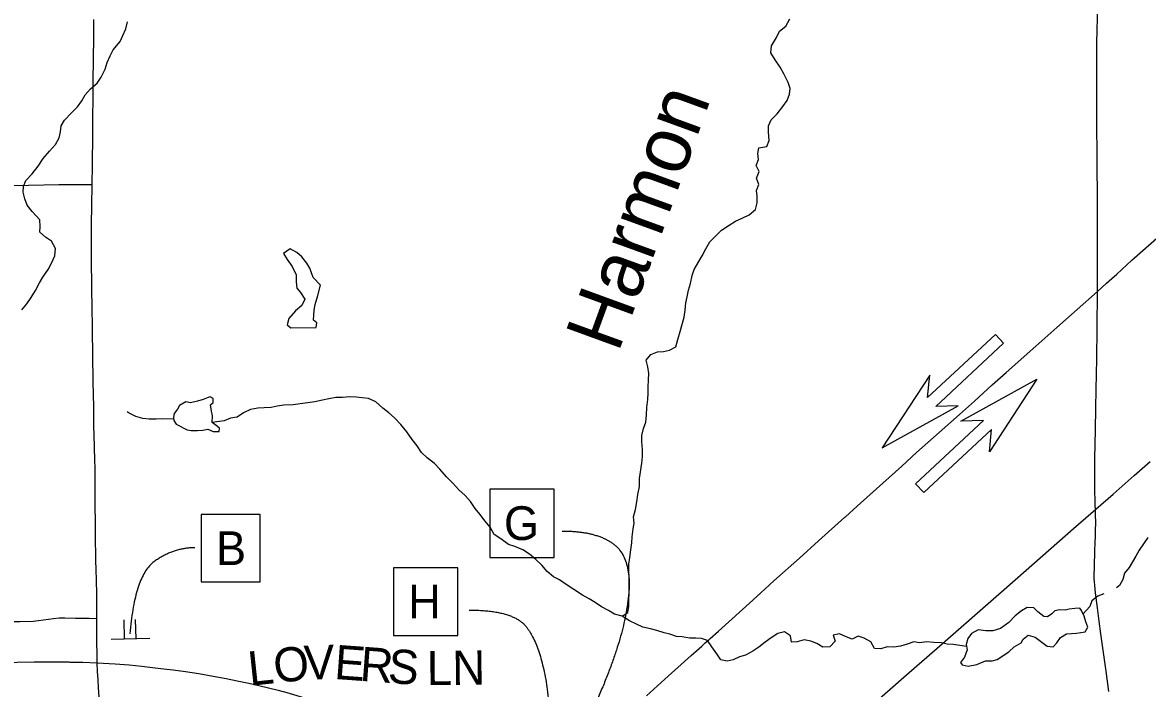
# Model space of a CAD drawing. Extents: x 0 to 34, y 0 to 22.
# Drawn here: x 2.507 to 7.177, y 6.648 to 9.413 of the extents above; entities that cross this region are included whole.
import ezdxf

# ---------------------------------------------------------------- set-up
doc = ezdxf.new("R2010")
doc.units = 0
for name, color, linetype in [('GM_X_City_Street', 7, 'Continuous'), ('GM_X_County_Road', 7, 'Continuous'), ('GM_X_County_Road_Text', 7, 'Continuous'), ('GM_X_Minor_Lake', 7, 'Continuous'), ('GM_X_Minor_River', 7, 'Continuous'), ('GM_X_Minor_River_Text', 7, 'Continuous'), ('GM_X_Rail_Line', 7, 'Continuous'), ('GM_X_State_Route', 7, 'Continuous'), ('GM_X_Township_Road', 7, 'Continuous'), ('PM_P_Cells', 7, 'Continuous'), ('SH_Text', 7, 'Continuous'), ('SN_P_Signs', 7, 'Continuous')]:
    doc.layers.add(name, color=color, linetype=linetype)

msp = doc.modelspace()

# ---------------------------------------------------------------- linework, layer by layer
at = {"layer": 'GM_X_City_Street'}
msp.add_lwpolyline([(2.1137, 6.9234), (2.2411, 6.9239), (2.3094, 6.9254), (2.3839, 6.9269), (2.4568, 6.927), (2.4957, 6.9269), (2.5516, 6.9283), (2.5732, 6.9304), (2.6362, 6.9394), (2.6593, 6.9416), (2.6826, 6.9422), (2.727, 6.941), (2.7835, 6.9399), (2.8154, 6.9392)], dxfattribs=at)
at = {"layer": 'GM_X_County_Road'}
for points in [[(6.9691, 8.2961), (6.9698, 8.5029), (6.9698, 8.5248), (6.9697, 8.5601), (6.9694, 8.6093), (6.9695, 8.6402), (6.9679, 8.8711), (6.9668, 8.9812), (6.9662, 9.0699), (6.9664, 9.1041), (6.9661, 9.1475), (6.9663, 9.1956), (6.9665, 9.2622), (6.9667, 9.3286), (6.9706, 9.4838)], [(6.9604, 7.4147), (6.9589, 7.4813), (6.9591, 7.6037), (6.961, 7.7219), (6.9626, 7.812), (6.9636, 7.8897), (6.9662, 8.0172), (6.9685, 8.1446), (6.9691, 8.2961)], [(7.0166, 6.6358), (7.0053, 6.7207), (6.9833, 6.8756), (6.9767, 6.928), (6.9696, 6.9835), (6.9614, 7.0451), (6.958, 7.0755), (6.9566, 7.0932), (6.9563, 7.1018), (6.9563, 7.1151), (6.957, 7.155), (6.9589, 7.2195), (6.9603, 7.2537), (6.9612, 7.2826), (6.9615, 7.2985), (6.962, 7.3418), (6.9618, 7.3648), (6.9612, 7.3858), (6.9604, 7.4147)], [(2.8208, 6.6847), (2.8191, 6.7188), (2.8178, 6.755)], [(2.827, 6.5951), (2.8224, 6.6514), (2.8208, 6.6847)]]:
    msp.add_lwpolyline(points, dxfattribs=at)
at = {"layer": 'GM_X_Minor_Lake'}
for p, q in [((3.6217, 8.1462), (3.7258, 8.1465)), ((3.1453, 7.7459), (3.191, 7.7218)), ((6.6015, 6.8011), (6.624, 6.8213))]:
    msp.add_line(p, q, dxfattribs=at)
for points in [[(3.7258, 8.1465), (3.7285, 8.1665), (3.7151, 8.1768), (3.7167, 8.1976), (3.7184, 8.2185), (3.7219, 8.2423), (3.7338, 8.2795), (3.7437, 8.3223), (3.7131, 8.3542), (3.6993, 8.3939), (3.6868, 8.4137), (3.6666, 8.4409), (3.6465, 8.4587), (3.6189, 8.4736), (3.5907, 8.4543), (3.6052, 8.4298), (3.6264, 8.3997), (3.6438, 8.3657), (3.6432, 8.3363), (3.6454, 8.3107), (3.6617, 8.2928), (3.679, 8.2646), (3.667, 8.2388), (3.6408, 8.2157), (3.6127, 8.185), (3.6055, 8.1574), (3.6217, 8.1462)], [(3.191, 7.7218), (3.2071, 7.7191), (3.2336, 7.7194), (3.2554, 7.7206), (3.2762, 7.7247), (3.299, 7.7154), (3.3236, 7.7157), (3.3254, 7.729), (3.3168, 7.7356), (3.2939, 7.7524), (3.2954, 7.7809), (3.2914, 7.7998), (3.2873, 7.8254), (3.2986, 7.8359), (3.2993, 7.8521), (3.2869, 7.8595), (3.2775, 7.8566), (3.2568, 7.8487), (3.2332, 7.8409), (3.2039, 7.8348), (3.1849, 7.8384), (3.1586, 7.8229), (3.1512, 7.8086), (3.1372, 7.7895), (3.1336, 7.7752), (3.1356, 7.761), (3.1453, 7.7459)], [(6.624, 6.8213), (6.6532, 6.8378), (6.6615, 6.8531), (6.6812, 6.8694), (6.7106, 6.8612), (6.7335, 6.8454), (6.7603, 6.8248), (6.7849, 6.8213), (6.8009, 6.8376), (6.8157, 6.8606), (6.8411, 6.8751), (6.8828, 6.8784), (6.9177, 6.8836), (6.9289, 6.9036), (6.9211, 6.9254), (6.9142, 6.9481), (6.9035, 6.9717), (6.8967, 6.982), (6.875, 6.9808), (6.8523, 6.9777), (6.8353, 6.9737), (6.8116, 6.9744), (6.7918, 6.9704), (6.7806, 6.9579), (6.7618, 6.9453), (6.7466, 6.9471), (6.7218, 6.9667), (6.7055, 6.9836), (6.678, 6.9842), (6.6545, 6.9707), (6.6282, 6.9504), (6.6011, 6.9226), (6.5673, 6.8975), (6.5352, 6.8877), (6.5058, 6.8873), (6.4745, 6.8917), (6.4463, 6.8771), (6.4314, 6.8561), (6.425, 6.8313), (6.4281, 6.8095), (6.4181, 6.779), (6.4013, 6.757), (6.408, 6.7467), (6.4327, 6.7412), (6.4686, 6.7474), (6.5053, 6.763), (6.5319, 6.7633), (6.5526, 6.7692), (6.6015, 6.8011)]]:
    msp.add_lwpolyline(points, dxfattribs=at)
at = {"layer": 'GM_X_Minor_River'}
for points in [[(2.5045, 8.2205), (2.5251, 8.2454), (2.5437, 8.2712), (2.5614, 8.3009), (2.5771, 8.3324), (2.591, 8.3563), (2.6143, 8.3878), (2.6273, 8.4146), (2.6421, 8.4442), (2.6446, 8.4755), (2.6281, 8.5057), (2.6033, 8.5215), (2.5794, 8.5421), (2.5801, 8.5668), (2.5789, 8.5934), (2.5472, 8.6281), (2.527, 8.6544), (2.5163, 8.6809), (2.5094, 8.7083), (2.511, 8.733), (2.5211, 8.7578), (2.5473, 8.7847), (2.5725, 8.8163), (2.593, 8.8488), (2.6191, 8.8785), (2.6444, 8.9063), (2.6592, 8.934), (2.6646, 8.9588), (2.6672, 8.9844), (2.6811, 9.0083), (2.7111, 9.0381), (2.7354, 9.063), (2.7541, 9.0879), (2.767, 9.1128), (2.7895, 9.1377), (2.8167, 9.1617), (2.8344, 9.1857), (2.851, 9.2191), (2.8592, 9.2467), (2.8712, 9.2753), (2.8833, 9.2992), (2.9122, 9.3346), (2.9233, 9.3594), (2.9362, 9.3871), (2.9435, 9.4166)], [(4.9959, 6.9485), (5.0204, 6.964), (5.0239, 6.9896), (5.0236, 7.0152), (5.0252, 7.0428), (5.0267, 7.0713), (5.0274, 7.0988), (5.0241, 7.132), (5.0247, 7.1643), (5.0282, 7.1918), (5.0326, 7.2241), (5.036, 7.2536), (5.0386, 7.2783), (5.042, 7.3106), (5.0464, 7.3353), (5.0433, 7.3609), (5.0515, 7.3914), (5.0578, 7.4228), (5.0621, 7.4542), (5.0684, 7.4874), (5.068, 7.5197), (5.0787, 7.5834), (5.0802, 7.6119), (5.0808, 7.6404), (5.0786, 7.6736), (5.0783, 7.6992), (5.0855, 7.7277), (5.0947, 7.7535), (5.0972, 7.7848), (5.0987, 7.8143), (5.1031, 7.8475), (5.1037, 7.8751), (5.1044, 7.8988), (5.106, 7.9292), (5.1066, 7.9558), (5.1025, 7.9842), (5.0965, 8.0116), (5.1152, 8.0356), (5.1425, 8.0454), (5.168, 8.0476), (5.1926, 8.0536), (5.219, 8.0671), (5.2271, 8.0976), (5.2372, 8.1309), (5.2535, 8.19), (5.2579, 8.2194), (5.2614, 8.2498), (5.2668, 8.2746), (5.2712, 8.3022), (5.2794, 8.3298), (5.2866, 8.3631), (5.2948, 8.3878), (5.3143, 8.4213), (5.3292, 8.4452), (5.344, 8.4738), (5.3598, 8.5025), (5.3832, 8.5265), (5.4085, 8.5515), (5.4404, 8.5718), (5.4668, 8.5891), (5.4979, 8.6028), (5.5233, 8.6145), (5.5495, 8.6366), (5.5568, 8.6652), (5.5565, 8.6917), (5.5543, 8.7164), (5.5635, 8.7412), (5.5547, 8.7676), (5.5648, 8.7943), (5.5532, 8.8189), (5.5623, 8.8446), (5.5592, 8.8692), (5.5637, 8.893), (5.5968, 8.8981), (5.6069, 8.9229), (5.6036, 8.9599), (5.6043, 8.9836), (5.6144, 9.0084), (5.6397, 9.0344), (5.664, 9.0641), (5.6807, 9.0899), (5.6909, 9.1156), (5.6944, 9.1394), (5.6856, 9.164), (5.6681, 9.1998), (5.6517, 9.2272), (5.6315, 9.2582), (5.6141, 9.2875), (5.6166, 9.3169), (5.6371, 9.3513), (5.6491, 9.3771), (5.6753, 9.3983), (5.693, 9.4279)], [(3.8655, 7.8587), (3.8352, 7.8564), (3.8077, 7.8571), (3.7785, 7.851), (3.7529, 7.846), (3.7208, 7.838), (3.6915, 7.8339), (3.6603, 7.8297), (3.6301, 7.8265), (3.5922, 7.8251), (3.5648, 7.8201), (3.5393, 7.815), (3.5109, 7.8138), (3.4844, 7.8125), (3.4542, 7.8065), (3.424, 7.7928), (3.3978, 7.7745), (3.3703, 7.7713), (3.3449, 7.7596), (3.2939, 7.7524)], [(6.4263, 6.8226), (6.3986, 6.8272), (6.3701, 6.8316), (6.3455, 6.8323), (6.3218, 6.8377), (6.2896, 6.8392), (6.2611, 6.8427), (6.2309, 6.8385), (6.2072, 6.8421), (6.1789, 6.8322), (6.1524, 6.8243), (6.1241, 6.8202), (6.0966, 6.8218), (6.0702, 6.8129), (6.0437, 6.8145), (6.0292, 6.8419), (6.0006, 6.8577), (5.9759, 6.865), (5.9514, 6.8533), (5.9257, 6.8635), (5.8981, 6.8755), (5.8717, 6.8695), (5.8805, 6.8449), (5.859, 6.8209), (5.8296, 6.8206), (5.8048, 6.8355), (5.7792, 6.8447), (5.7516, 6.85), (5.7233, 6.8421), (5.6987, 6.8409), (5.6947, 6.8665), (5.6708, 6.8842), (5.6425, 6.8763), (5.6152, 6.8589), (5.5899, 6.8406), (5.5636, 6.8203), (5.5391, 6.8039), (5.509, 6.7874), (5.4836, 6.7795), (5.4572, 6.7678), (5.4317, 6.7618), (5.4061, 6.7672), (5.3897, 6.7917), (5.3685, 6.8219), (5.3502, 6.8482), (5.3255, 6.8555), (5.3018, 6.8571), (5.2753, 6.8568), (5.2459, 6.8631), (5.2213, 6.8648), (5.1947, 6.8739), (5.1709, 6.8793), (5.1405, 6.8894), (5.1139, 6.8958), (5.0826, 6.903), (5.0559, 6.916), (5.0264, 6.9289), (4.9959, 6.9485), (4.9646, 6.9576), (4.9398, 6.9716), (4.9112, 6.9874), (4.8845, 7.0051), (4.8588, 7.02), (4.8321, 7.0358), (4.7605, 7.0824), (4.7357, 7.0992), (4.7119, 7.1122), (4.6852, 7.1337), (4.6631, 7.161), (4.6382, 7.1844), (4.6114, 7.2059), (4.5838, 7.2246), (4.5514, 7.2385), (4.5248, 7.2457), (4.4924, 7.2691), (4.4656, 7.2878), (4.4482, 7.3179), (4.4271, 7.3424), (4.405, 7.3715), (4.3858, 7.396), (4.3665, 7.4252), (4.3454, 7.4496), (4.3187, 7.473), (4.2937, 7.5002), (4.2679, 7.5265), (4.2391, 7.5584), (4.218, 7.5829), (4.1874, 7.6053), (4.1635, 7.6278), (4.1452, 7.6551), (4.125, 7.6824), (4.1029, 7.7134), (4.0779, 7.7445), (4.0511, 7.7717), (4.0272, 7.7932), (4.0023, 7.8128), (3.9736, 7.8381), (3.9432, 7.852), (3.9176, 7.8555), (3.8929, 7.8581), (3.8655, 7.8587)], [(3.1347, 7.7671), (3.0892, 7.768), (3.0617, 7.7658), (3.0333, 7.7664), (3.0068, 7.7699), (2.9773, 7.7772), (2.9497, 7.792), (2.9421, 7.7976)], [(7.1784, 7.2757), (7.1607, 7.249), (7.1421, 7.2222), (7.1282, 7.1983), (7.1152, 7.1744), (7.1012, 7.1505), (7.0816, 7.1266), (7.0753, 7.1009), (7.0604, 7.076), (7.0482, 7.0664)], [(6.9964, 7.0411), (6.971, 7.0323), (6.9466, 7.013), (6.9383, 6.9882), (6.9094, 6.9586)]]:
    msp.add_lwpolyline(points, dxfattribs=at)
at = {"layer": 'GM_X_Rail_Line'}
msp.add_lwpolyline([(4.631, 5.3498), (4.7, 5.4104), (4.8512, 5.5428), (5.0065, 5.6787), (5.1355, 5.7912), (5.3567, 5.9853), (5.7346, 6.3169), (6.0085, 6.5567), (6.1878, 6.7145), (6.2934, 6.806), (6.5822, 7.0593), (6.7081, 7.1697), (6.8704, 7.3121), (7.0343, 7.4557), (7.122, 7.532), (7.1883, 7.5902)], dxfattribs=at)
at = {"layer": 'GM_X_State_Route'}
for points in [[(2.8141, 7.0959), (2.8139, 7.1085), (2.8135, 7.1332), (2.8121, 7.1889), (2.8112, 7.2215), (2.8107, 7.2464), (2.8106, 7.2727), (2.8103, 7.3427), (2.8091, 7.4023), (2.8092, 7.4415), (2.8089, 7.4539), (2.8086, 7.4679), (2.8087, 7.4881), (2.8091, 7.5284), (2.8088, 7.561), (2.8079, 7.5981), (2.8046, 7.7016), (2.8038, 7.7357), (2.8032, 7.7822), (2.8028, 7.8179), (2.8011, 7.9204), (2.8008, 7.9561), (2.7997, 7.9995), (2.7987, 8.0583), (2.7981, 8.1095), (2.7972, 8.1607), (2.7963, 8.2166), (2.7931, 8.4232), (2.793, 8.5087), (2.7936, 8.5755), (2.7951, 8.6515), (2.796, 8.7413), (2.7971, 8.8214), (2.7991, 8.9491), (2.8007, 9.1686), (2.8027, 9.3519), (2.8034, 9.4007), (2.8036, 9.4256)], [(7.0288, 8.3504), (7.0492, 8.3686), (7.1126, 8.426), (7.2264, 8.528)], [(6.9691, 8.2961), (7.0065, 8.3306), (7.0288, 8.3504)], [(6.5327, 7.9084), (6.5902, 7.9601), (6.7133, 8.0694), (6.8002, 8.1471), (6.9691, 8.2961)], [(6.1571, 7.5718), (6.2188, 7.6276), (6.3126, 7.7112), (6.3961, 7.7856), (6.4586, 7.8416), (6.5327, 7.9084)], [(5.9232, 7.3613), (5.9723, 7.4055), (6.0253, 7.4534), (6.1571, 7.5718)], [(5.5409, 7.0162), (5.5727, 7.0455), (5.6264, 7.0948), (5.7319, 7.1888), (5.8111, 7.261), (5.9214, 7.3597), (5.9232, 7.3613)], [(2.8151, 7.0277), (2.8151, 7.0432), (2.8141, 7.0959)], [(2.8178, 6.755), (2.8166, 6.8031), (2.8162, 6.8275), (2.8154, 6.8759), (2.8154, 6.9392), (2.8154, 6.9491), (2.8151, 6.9819), (2.8151, 7.0277)], [(5.0969, 6.6184), (5.173, 6.6866), (5.2826, 6.7852), (5.3265, 6.8246), (5.3415, 6.838), (5.3555, 6.8503), (5.3622, 6.8566), (5.3958, 6.8865), (5.5391, 7.0146), (5.5409, 7.0162)], [(1.8637, 6.7516), (2.0663, 6.7535), (2.1797, 6.7548), (2.2838, 6.7557), (2.4143, 6.757), (2.5556, 6.7585), (2.6349, 6.7588), (2.6992, 6.7585)], [(2.6992, 6.7585), (2.7042, 6.7584), (2.7575, 6.7574), (2.8178, 6.755)], [(2.8178, 6.755), (2.8925, 6.7505), (2.9497, 6.7461), (3.0027, 6.741), (3.0574, 6.7348), (3.0939, 6.7305), (3.1331, 6.7259), (3.1841, 6.719), (3.2394, 6.7103), (3.2992, 6.6996), (3.3531, 6.6894), (3.3985, 6.6803), (3.4461, 6.6701), (3.4886, 6.6606), (3.5279, 6.6513), (3.5678, 6.6414), (3.6046, 6.6313), (3.7061, 6.601)]]:
    msp.add_lwpolyline(points, dxfattribs=at)
at = {"layer": 'GM_X_Township_Road'}
msp.add_lwpolyline([(1.6712, 8.7318), (1.696, 8.7322), (1.7472, 8.7326), (1.7999, 8.7329), (2.0464, 8.7341), (2.161, 8.7337), (2.4323, 8.736), (2.5319, 8.7372), (2.6576, 8.7405), (2.7068, 8.7409), (2.74, 8.7413), (2.796, 8.7413)], dxfattribs=at)
at = {"layer": 'PM_P_Cells'}
for p, q in [((6.5457, 8.1183), (6.2638, 7.8561)), ((6.2979, 7.8195), (6.5798, 8.0817)), ((6.5798, 8.0817), (6.5457, 8.1183)), ((6.5628, 8.1), (6.5628, 8.1)), ((6.273, 7.9491), (6.0758, 7.6471)), ((6.2638, 7.8561), (6.273, 7.9491)), ((6.4027, 7.7583), (6.7181, 7.9331)), ((6.7181, 7.9331), (6.5209, 7.6312)), ((6.7181, 7.9331), (6.7181, 7.9331)), ((6.0758, 7.6471), (6.3912, 7.8219)), ((6.3912, 7.8219), (6.2979, 7.8195)), ((6.2141, 7.4985), (6.496, 7.7607)), ((6.496, 7.7607), (6.4027, 7.7583)), ((6.5301, 7.7241), (6.2482, 7.4619)), ((6.5209, 7.6312), (6.5301, 7.7241)), ((6.0758, 7.6471), (6.0758, 7.6471)), ((6.2482, 7.4619), (6.2141, 7.4985)), ((6.2311, 7.4802), (6.2311, 7.4802))]:
    msp.add_line(p, q, dxfattribs=at)
at = {"layer": 'SH_Text'}
for points in [[(4.4475, 7.1928), (4.7135, 7.1928), (4.7135, 7.4761), (4.4475, 7.4761)], [(3.2495, 7.0907), (3.4936, 7.0907), (3.4936, 7.3701), (3.2495, 7.3701)], [(4.0471, 6.8686), (4.3146, 6.8686), (4.3146, 7.1493), (4.0471, 7.1493)]]:
    msp.add_lwpolyline(points, close=True, dxfattribs=at)
for points in [[(4.7476, 7.3021), (4.9036, 7.3021), (5.0431, 7.1726), (4.9933, 6.8204), (4.8728, 6.5567)], [(3.2231, 7.2328), (3.132, 7.2328), (2.9726, 7.1151), (2.953, 6.8759)], [(4.362, 6.9738), (4.5413, 6.9738), (4.6508, 6.8409), (4.7073, 6.5319), (4.6706, 6.3348)]]:
    msp.add_open_spline(points, degree=2, dxfattribs=at)
at = {"layer": 'SN_P_Signs'}
for p, q in [((2.9311, 6.8532), (2.9289, 6.9331)), ((2.9791, 6.8545), (2.9769, 6.9345)), ((3.0351, 6.8561), (2.8752, 6.8516)), ((2.9551, 6.8538), (2.9551, 6.8538)), ((2.9551, 6.8538), (2.9551, 6.8538))]:
    msp.add_line(p, q, dxfattribs=at)

# ---------------------------------------------------------------- texts
at = {"layer": 'GM_X_County_Road_Text'}
for s, height, rotation, p in [('O', 0.142, 6.0876, (3.5564, 6.6706)), ('V', 0.142, 2.1169, (3.6781, 6.6837)), ('E', 0.142, 355.8478, (3.7989, 6.6884)), ('R', 0.142, 355.777, (3.9048, 6.6807)), ('L', 0.142, 6.1187, (3.4508, 6.6593)), ('S', 0.142, 355.7816, (4.0212, 6.6721)), ('LN', 0.14205, 0.5134, (4.1857, 6.6623))]:
    msp.add_text(s, height=height, rotation=rotation, dxfattribs=at).set_placement(p)
at = {"layer": 'GM_X_Minor_River_Text'}
msp.add_text('Harmon', height=0.23678, rotation=69.9863, dxfattribs=at).set_placement((4.9799, 8.038))
at = {"layer": 'SH_Text'}
for s, p in [('G', (4.5057, 7.2648)), ('B', (3.3104, 7.1607)), ('H', (4.1083, 6.9393))]:
    msp.add_text(s, height=0.14, dxfattribs=at).set_placement(p)

doc.saveas('drawing.dxf')
